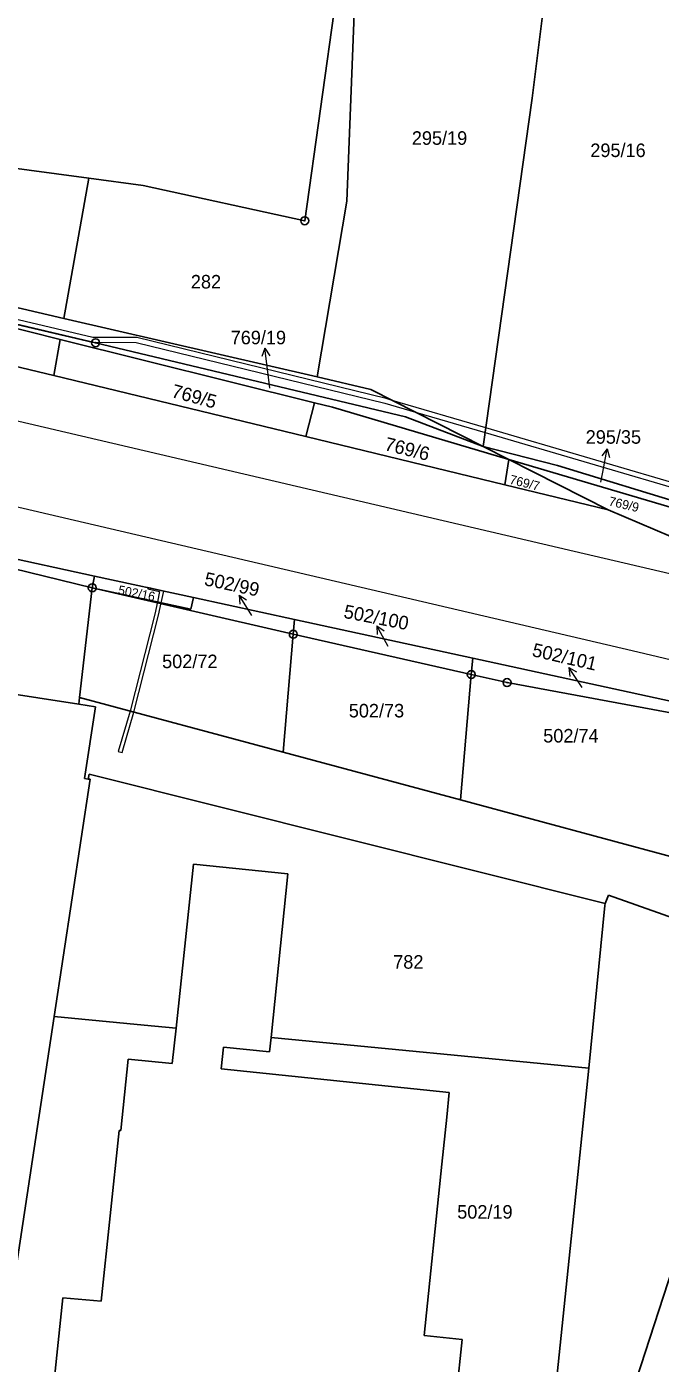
# Model space of a CAD drawing. Extents: x -701211 to -698780, y -1014269 to -1012378.
# Drawn here: x -700156.3 to -700076.7, y -1012806.8 to -1012639 of the extents above; entities that cross this region are included whole.
import ezdxf
from ezdxf.enums import TextEntityAlignment as Align

# ---------------------------------------------------------------- set-up
doc = ezdxf.new("R2010")
doc.units = 0
doc.header["$LTSCALE"] = 0.68
for name, color, linetype, lineweight in [('1', 7, 'Continuous', 25), ('13', 7, 'Continuous', 13), ('4', 7, 'Continuous', 13), ('7', 7, 'Continuous', 13), ('8', 7, 'Continuous', 25)]:
    doc.layers.add(name, color=color, linetype=linetype, lineweight=lineweight)
doc.layers.add('2', color=7, linetype='Continuous')

msp = doc.modelspace()

# ---------------------------------------------------------------- linework, layer by layer
at = {"layer": '1'}
for p, q in [((-700114.21, -1012612.36), (-700121.37, -1012663.33)), ((-700116.06, -1012660.88), (-700114.21, -1012612.36)), ((-700092.82, -1012647.95), (-700088.97, -1012617.37)), ((-700098.96, -1012691.69), (-700092.82, -1012647.95)), ((-700148.46, -1012657.99), (-700175.55, -1012654.39)), ((-700148.46, -1012657.99), (-700151.6, -1012675.6)), ((-700141.64, -1012658.89), (-700148.46, -1012657.99)), ((-700121.37, -1012663.33), (-700141.64, -1012658.89)), ((-700116.06, -1012660.88), (-700119.82, -1012682.96)), ((-700151.6, -1012675.6), (-700177.89, -1012669.51)), ((-700152.07, -1012678.24), (-700178.23, -1012671.71)), ((-700167.11, -1012674.11), (-700147.63, -1012678.66)), ((-700119.82, -1012682.96), (-700151.6, -1012675.6)), ((-700152.88, -1012682.79), (-700178.97, -1012676.47)), ((-700152.88, -1012682.79), (-700152.07, -1012678.24)), ((-700120.15, -1012686.2), (-700152.07, -1012678.24)), ((-700147.63, -1012678.66), (-700108.73, -1012687.96)), ((-700121.22, -1012690.45), (-700152.88, -1012682.79)), ((-700113.08, -1012684.52), (-700119.82, -1012682.96)), ((-700098.96, -1012691.69), (-700113.08, -1012684.52)), ((-700121.22, -1012690.45), (-700120.15, -1012686.2)), ((-700117.9, -1012686.76), (-700120.15, -1012686.2)), ((-700095.74, -1012693.32), (-700117.9, -1012686.76)), ((-700108.73, -1012687.96), (-700098.96, -1012691.69)), ((-700096.24, -1012696.5), (-700121.22, -1012690.45)), ((-700098.96, -1012691.69), (-700089.63, -1012694.09)), ((-700095.74, -1012693.32), (-700098.96, -1012691.69)), ((-700095.74, -1012693.32), (-700096.24, -1012696.5)), ((-700095.74, -1012693.32), (-700083.28, -1012699.64)), ((-700072.75, -1012700.12), (-700095.74, -1012693.32)), ((-700089.63, -1012694.09), (-700072.66, -1012699.28)), ((-700083.28, -1012699.64), (-700096.24, -1012696.5)), ((-700073.42, -1012703.83), (-700083.28, -1012699.64)), ((-700148.05, -1012709.44), (-700176.46, -1012702.49)), ((-700147.77, -1012707.96), (-700176.25, -1012701.77)), ((-700148.05, -1012709.44), (-700147.77, -1012707.96)), ((-700147.77, -1012707.96), (-700135.33, -1012710.66)), ((-700148.05, -1012709.44), (-700149.64, -1012723.21)), ((-700122.8, -1012715.28), (-700148.05, -1012709.44)), ((-700148.05, -1012709.44), (-700135.65, -1012712.13)), ((-700135.65, -1012712.13), (-700135.33, -1012710.66)), ((-700122.64, -1012713.42), (-700135.33, -1012710.66)), ((-700122.64, -1012713.42), (-700122.8, -1012715.28)), ((-700100.27, -1012718.28), (-700122.64, -1012713.42)), ((-700122.8, -1012715.28), (-700124.07, -1012730.09)), ((-700100.45, -1012720.33), (-700122.8, -1012715.28)), ((-700100.27, -1012718.28), (-700100.45, -1012720.33)), ((-700073.52, -1012724.09), (-700100.27, -1012718.28)), ((-700178.3, -1012719.64), (-700149.75, -1012724.06)), ((-700100.45, -1012720.33), (-700101.82, -1012736.08)), ((-700095.96, -1012721.34), (-700100.45, -1012720.33)), ((-700073.61, -1012725.48), (-700095.96, -1012721.34)), ((-700149.75, -1012724.06), (-700149.64, -1012723.21)), ((-700149.75, -1012724.06), (-700147.66, -1012724.38)), ((-700124.07, -1012730.09), (-700149.64, -1012723.21)), ((-700147.66, -1012724.38), (-700149.04, -1012733.39)), ((-700101.82, -1012736.08), (-700124.07, -1012730.09)), ((-700148.3, -1012733.5), (-700152.82, -1012763.29)), ((-700148.57, -1012733.46), (-700148.3, -1012733.5)), ((-700148.43, -1012732.84), (-700083.62, -1012749.09)), ((-700074.79, -1012743.36), (-700101.82, -1012736.08)), ((-700123.5, -1012745.39), (-700125.6, -1012765.92)), ((-700085.71, -1012769.77), (-700083.69, -1012749.33)), ((-700083.69, -1012749.33), (-700083.62, -1012749.09)), ((-700083.62, -1012749.09), (-700083.22, -1012748.07)), ((-700062.23, -1012755.49), (-700083.22, -1012748.07)), ((-700152.82, -1012763.29), (-700155.55, -1012781.25)), ((-700141.55, -1012764.38), (-700152.82, -1012763.29)), ((-700137.53, -1012764.77), (-700141.55, -1012764.38)), ((-700138.01, -1012769.21), (-700137.53, -1012764.77)), ((-700125.6, -1012765.92), (-700125.79, -1012767.75)), ((-700085.71, -1012769.77), (-700125.6, -1012765.92)), ((-700131.56, -1012767.15), (-700131.84, -1012769.85)), ((-700125.79, -1012767.75), (-700131.56, -1012767.15)), ((-700143.53, -1012768.63), (-700144.47, -1012777.63)), ((-700138.01, -1012769.21), (-700143.53, -1012768.63)), ((-700066.91, -1012769.42), (-700094.37, -1012854)), ((-700103.22, -1012772.85), (-700131.84, -1012769.85)), ((-700094.37, -1012854), (-700085.71, -1012769.77)), ((-700103.52, -1012775.94), (-700103.22, -1012772.85)), ((-700104.14, -1012781.86), (-700103.52, -1012775.94)), ((-700146.93, -1012799.07), (-700144.67, -1012777.61)), ((-700144.67, -1012777.61), (-700144.47, -1012777.63)), ((-700155.55, -1012781.25), (-700163.63, -1012834.2)), ((-700104.14, -1012781.86), (-700106.36, -1012803.38)), ((-700154.85, -1012827.93), (-700151.75, -1012798.62)), ((-700151.75, -1012798.62), (-700146.93, -1012799.07)), ((-700106.36, -1012803.38), (-700101.58, -1012803.88)), ((-700101.58, -1012803.88), (-700104.66, -1012833.2))]:
    msp.add_line(p, q, dxfattribs=at)
for points in [[(-700149.04, -1012733.39), (-700148.57, -1012733.46), (-700148.43, -1012732.84)], [(-700137.53, -1012764.77), (-700135.33, -1012744.16), (-700123.5, -1012745.39)]]:
    msp.add_lwpolyline(points, dxfattribs=at)
at = {"layer": '13'}
msp.add_lwpolyline([(-700186.81, -1012669.49), (-700148.04, -1012678.6), (-700142.53, -1012678.61), (-700111.3, -1012686.25), (-700107.44, -1012687.38), (-700110.37, -1012685.9), (-700111.14, -1012685.67), (-700142.45, -1012678.01), (-700147.96, -1012678), (-700186.61, -1012668.89)], dxfattribs=at)
for points in [[(-700110.37, -1012685.9), (-700107.44, -1012687.38), (-700098.72, -1012689.95), (-700072.49, -1012697.65), (-700072.42, -1012697.04), (-700098.63, -1012689.35)], [(-700139.6, -1012709.89), (-700139.87, -1012711.21), (-700139.38, -1012711.32), (-700139.08, -1012709.85), (-700141.09, -1012709.41), (-700141.08, -1012709.59)], [(-700140.19, -1012712.77), (-700143.3, -1012724.92), (-700144.78, -1012730), (-700144.3, -1012730.14), (-700142.82, -1012725.05), (-700139.71, -1012712.89), (-700139.38, -1012711.32), (-700139.87, -1012711.21)]]:
    msp.add_lwpolyline(points, close=True, dxfattribs=at)
at = {"layer": '4'}
for p, q in [((-700087.55, -1012704.87), (-700212.69, -1012675.59)), ((-700196.3, -1012690.18), (-700080.25, -1012717.33)), ((-699962.33, -1012734.1), (-700087.55, -1012704.87)), ((-700080.25, -1012717.33), (-699965.64, -1012744.18))]:
    msp.add_line(p, q, dxfattribs=at)
at = {"layer": '7'}
for p, q in [((-700126.366, -1012679.351), (-700126.741, -1012680.406)), ((-700083.377, -1012691.974), (-700084.06, -1012692.862)), ((-700129.62, -1012710.375), (-700129.514, -1012711.49)), ((-700112.325, -1012714.205), (-700112.277, -1012715.324)), ((-700088.208, -1012719.462), (-700088.063, -1012720.572))]:
    msp.add_line(p, q, dxfattribs=at)
for points in [[(-700125.73, -1012684.37), (-700126, -1012682.33), (-700126.366, -1012679.351), (-700125.747, -1012680.284)], [(-700084.19, -1012696.18), (-700083.95, -1012694.92), (-700083.377, -1012691.974), (-700083.077, -1012693.053)], [(-700128.03, -1012712.92), (-700129.62, -1012710.375), (-700128.665, -1012710.959)], [(-700110.87, -1012716.83), (-700112.325, -1012714.205), (-700111.401, -1012714.838)], [(-700086.53, -1012721.95), (-700088.208, -1012719.462), (-700087.233, -1012720.012)]]:
    msp.add_lwpolyline(points, dxfattribs=at)
at = {"layer": '8'}
for centre, radius in [((-700121.37, -1012663.3299), 0.5), ((-700121.37, -1012663.3299), 0.0303), ((-700147.63, -1012678.6599), 0.5), ((-700147.63, -1012678.6599), 0.0303), ((-700148.05, -1012709.4399), 0.5), ((-700148.05, -1012709.4399), 0.0303), ((-700122.8, -1012715.2799), 0.5), ((-700122.8, -1012715.2799), 0.0303), ((-700100.45, -1012720.3299), 0.5), ((-700100.45, -1012720.3299), 0.0303), ((-700095.96, -1012721.3399), 0.5), ((-700095.96, -1012721.3399), 0.0303)]:
    msp.add_circle(centre, radius, dxfattribs=at)

# ---------------------------------------------------------------- texts
at = {"layer": '2'}
for s, p in [('295/19', (-700104.44, -1012653.795)), ('295/16', (-700082.03, -1012655.335)), ('282', (-700133.769, -1012671.845)), ('769/19', (-700127.19, -1012678.855)), ('295/35', (-700082.61, -1012691.345)), ('502/72', (-700135.8, -1012719.535)), ('502/73', (-700112.36, -1012725.725)), ('502/74', (-700087.94, -1012728.875)), ('782', (-700108.359, -1012757.285))]:
    msp.add_text(s, height=1.7, dxfattribs=at).set_placement(p, align=Align.CENTER)
for s, rotation, p in [('769/5', 345, (-700138.209, -1012685.47)), ('769/6', 346, (-700111.452, -1012692.132))]:
    msp.add_text(s, height=1.7, rotation=rotation, dxfattribs=at).set_placement(p)
for s, height, rotation, p in [('769/7', 1.14, 346, (-700093.8784, -1012696.8036)), ('769/9', 1.14, 347, (-700081.4087, -1012699.5119)), ('502/99', 1.7, 348, (-700130.6782, -1012709.8249)), ('502/16', 1.14, 349, (-700142.5788, -1012710.6803)), ('502/100', 1.7, 349, (-700112.5377, -1012713.9828)), ('502/101', 1.7, 347, (-700088.9082, -1012718.936))]:
    msp.add_text(s, height=height, rotation=rotation, dxfattribs=at).set_placement(p, align=Align.CENTER)
msp.add_text('502/19', height=1.7, dxfattribs=at).set_placement((-700102.22, -1012788.685))

doc.saveas('drawing.dxf')
